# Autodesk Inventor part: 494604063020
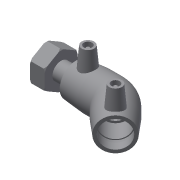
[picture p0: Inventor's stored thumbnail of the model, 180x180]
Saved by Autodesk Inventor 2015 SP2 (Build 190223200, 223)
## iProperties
Created: 2017-06
Part Number: 494604063020
Material: Generic
Description: PLASSON 45° ELBOW FEMALE FREE NUT TRANSITION 63-2"
Document SubType Name: Modeling
Designer: KIM
Mass: 55.0731 g
Surface Area: 148.067 cm^2
Volume: 55.0731 cm^3
Density: 1 g/cm^3
Appearance: Default
Author: KIM
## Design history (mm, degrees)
derived "494604.ipt"
feature "Solid1::494604.ipt"
tag "TaggingFeature1"
body "Solid1"
other parameters: "d2" = 82, "d4" = 37, "d5" = 73.8, "d8" = 168 deg, "d10" = 22.8, "d11" = 7.6, "d29" = 59, "d30" = 15, "d31" = 51.8, "d34" = 5 deg, "d41" = 4, "d42" = 14, "d43" = 0, "d49" = 63, "d50" = 53.55, "d51" = 22.8, "d52" = 57.57, "d54" = 135 deg, "d86" = 36.9, "d87" = 135 deg, "d88" = 148, "d90" = 57, "d91" = 0, "d92" = 57, "d93" = 0, "d101" = 3, "d102" = 0, "d108" = 38, "d110" = 41, "d112" = 84.984, "d113" = 56.656, "d139" = 39.6592, "d140" = 38, "d141" = 20.5, "d142" = 2.05, "d143" = 4.1, "d144" = 16.4, "d145" = 45.3248, "d146" = 2.8328, "d150" = 0, "d151" = 3.15, "d_" = 63, "L_" = 189, "L_1" = 57, "D_" = 38, "A_" = 59, "d_2" = 12, "L_2" = 41, "G_" = 56.656, "D_1" = 82
